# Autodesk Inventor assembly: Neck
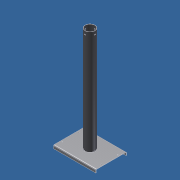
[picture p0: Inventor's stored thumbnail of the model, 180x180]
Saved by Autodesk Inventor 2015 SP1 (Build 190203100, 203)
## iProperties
Category: Mechanical Engineering Drawing and Design - CADD
Manager: Fábio Ricardo de Oliveira Souza
Company: SENAI - Serviço Nacional de Aprendizagem Industrial
Created: 2011-06
Part Number: Neck
Document SubType Name: Weldment
Designer: Guilherme Augusto Franco de Souza
Engineer: George Geraldo de Oliveia Silva
Authority: Fábio Ricardo de Oliveira Soza
Weld Material: Welded Stainless Steel, 440C
Description: Sub-assembly
Subject: WorldSkill 2011 - London, England
Author: Guilherme Augusto Franco de Souza
Revision Number: 00
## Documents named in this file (3)
- E:\Visitor Experience Project\WSI2015 - Visitor Experience Project\#46- Sheet Metal Technology\01- 3D Models\Outodoor Heater\2- Assemblies\Neck.iam
- E:\Visitor Experience Project\WSI2015 - Visitor Experience Project\#46- Sheet Metal Technology\01- 3D Models\Outodoor Heater\1- Parts\Simple base.ipt
- E:\Visitor Experience Project\WSI2015 - Visitor Experience Project\#46- Sheet Metal Technology\01- 3D Models\Outodoor Heater\1- Parts\Centre tube.ipt
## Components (2 placed, 2 different names)
1. Simple base:1 — Insert:1, Mate:1
2. Centre tube:1 — Insert:1, Mate:1
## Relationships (2: Insert 1, Mate 1)
- Insert:1: Simple base:1 ↔ Centre tube:1
- Mate:1: Simple base:1 ↔ Centre tube:1
